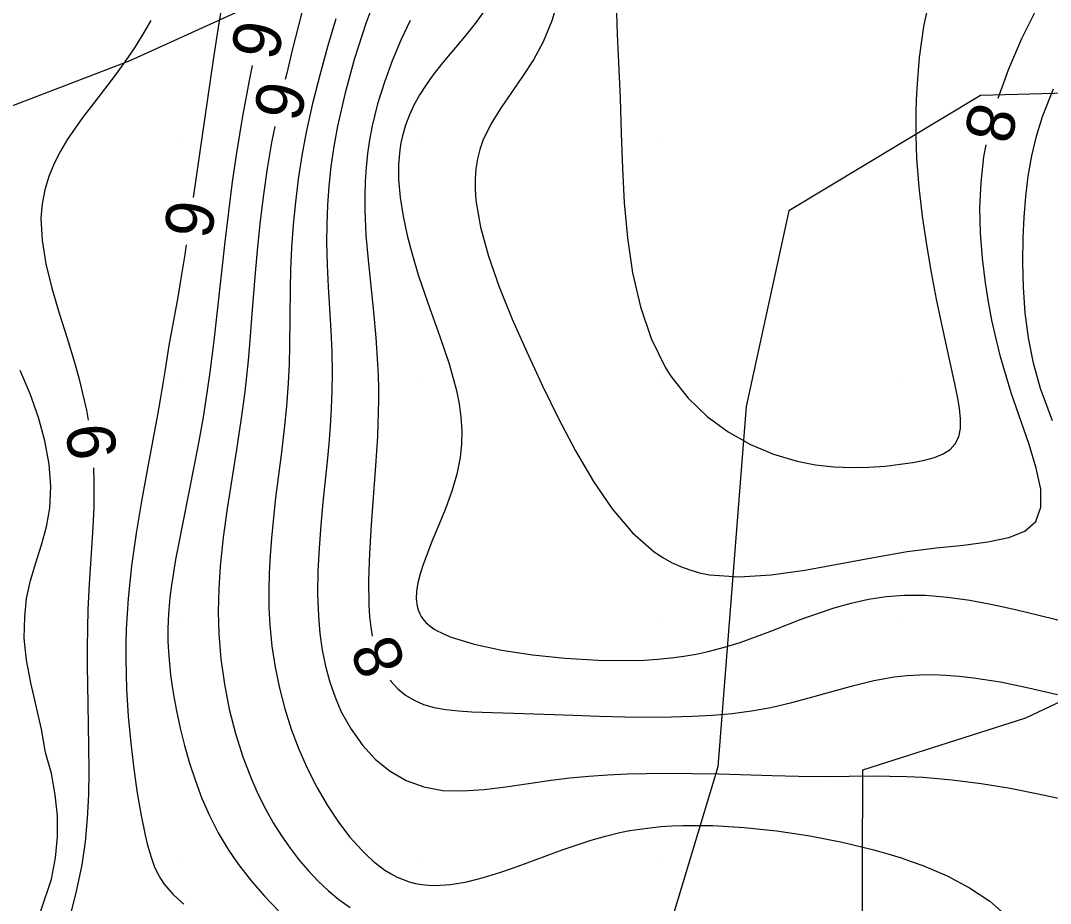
# Model space of a CAD drawing. Extents: x 2602990 to 2605851, y 618069 to 619180.
# Drawn here: x 2603123.31 to 2603166.25, y 618398.06 to 618434.86 of the extents above; entities that cross this region are included whole.
import ezdxf

# ---------------------------------------------------------------- set-up
doc = ezdxf.new("R2010")
doc.units = 0
for name, color, linetype in [('DTM Contours Major', 7, 'Continuous'), ('DTM Contours Major Text', 7, 'Continuous'), ('DTM Contours Minor', 7, 'Continuous'), ('DTM Contours Minor Text', 7, 'Continuous'), ('Exist DTM QL2 LIDAR Elevation Point', 7, 'Continuous'), ('PH Exist DTM Obscure Area', 7, 'Continuous')]:
    doc.layers.add(name, color=color, linetype=linetype)

msp = doc.modelspace()

# ---------------------------------------------------------------- linework, layer by layer
at = {"layer": 'DTM Contours Major'}
for points in [[(2603139.557, 618434.862), (2603139.169, 618434.042), (2603138.806, 618433.184), (2603138.478, 618432.296), (2603138.196, 618431.388), (2603137.969, 618430.469), (2603137.859, 618429.894), (2603137.773, 618429.316), (2603137.711, 618428.733), (2603137.672, 618428.145), (2603137.655, 618427.549), (2603137.659, 618426.945), (2603137.708, 618425.919), (2603137.795, 618424.869), (2603138.02, 618422.722), (2603138.122, 618421.636), (2603138.196, 618420.551), (2603138.216, 618420.05), (2603138.226, 618419.55), (2603138.228, 618419.048), (2603138.221, 618418.542), (2603138.206, 618418.033), (2603138.184, 618417.517), (2603138.11, 618416.302), (2603137.926, 618413.851), (2603137.851, 618412.664), (2603137.813, 618411.535), (2603137.828, 618410.489), (2603137.86, 618410.022), (2603137.91, 618409.58), (2603137.973, 618409.201)], [(2603138.722, 618407.366), (2603138.757, 618407.315), (2603139.038, 618407.006), (2603139.358, 618406.743), (2603139.716, 618406.525), (2603140.113, 618406.354), (2603140.557, 618406.227), (2603141.041, 618406.14), (2603141.562, 618406.085), (2603142.119, 618406.051), (2603144.295, 618405.98), (2603146.356, 618405.901), (2603147.429, 618405.865), (2603148.51, 618405.839), (2603149.584, 618405.828), (2603150.455, 618405.834), (2603151.311, 618405.858), (2603152.152, 618405.906), (2603152.979, 618405.98), (2603153.79, 618406.086), (2603154.587, 618406.227), (2603155.471, 618406.431), (2603156.339, 618406.666), (2603157.196, 618406.911), (2603158.045, 618407.145), (2603158.89, 618407.348), (2603159.736, 618407.499), (2603160.266, 618407.559), (2603160.8, 618407.592), (2603161.341, 618407.598), (2603161.893, 618407.579), (2603162.457, 618407.536), (2603163.036, 618407.469), (2603164.16, 618407.289), (2603165.332, 618407.05), (2603166.536, 618406.768)]]:
    msp.add_lwpolyline(points, dxfattribs=at)
at = {"layer": 'DTM Contours Minor'}
for points in [[(2603135.323, 618436.348), (2603134.637, 618433.625), (2603134.403, 618432.673), (2603134.338, 618432.399)], [(2603138.241, 618436.202), (2603137.708, 618434.734), (2603137.237, 618433.276), (2603136.839, 618431.845), (2603136.522, 618430.458), (2603136.368, 618429.607), (2603136.248, 618428.776), (2603136.161, 618427.963), (2603136.104, 618427.163), (2603136.074, 618426.374), (2603136.07, 618425.592), (2603136.093, 618424.673), (2603136.138, 618423.759), (2603136.245, 618421.946), (2603136.285, 618421.046), (2603136.302, 618420.152), (2603136.292, 618419.421), (2603136.261, 618418.691), (2603136.215, 618417.959), (2603136.155, 618417.223), (2603136.086, 618416.482), (2603135.915, 618414.784), (2603135.826, 618413.828), (2603135.752, 618412.867), (2603135.705, 618411.909), (2603135.692, 618410.96), (2603135.725, 618410.026), (2603135.788, 618409.315), (2603135.887, 618408.619), (2603136.023, 618407.942), (2603136.2, 618407.287), (2603136.418, 618406.656), (2603136.681, 618406.052), (2603137.086, 618405.321), (2603137.563, 618404.654), (2603138.109, 618404.065), (2603138.72, 618403.569), (2603139.39, 618403.18), (2603140.117, 618402.913), (2603140.912, 618402.773), (2603141.754, 618402.748), (2603142.634, 618402.806), (2603143.545, 618402.92), (2603145.427, 618403.198), (2603146.21, 618403.291), (2603146.999, 618403.365), (2603147.794, 618403.419), (2603148.597, 618403.457), (2603149.408, 618403.479), (2603150.228, 618403.486), (2603151.322, 618403.477), (2603152.428, 618403.454), (2603154.648, 618403.39), (2603155.75, 618403.366), (2603156.837, 618403.356), (2603158.877, 618403.372), (2603159.558, 618403.37), (2603160.245, 618403.355), (2603160.943, 618403.322), (2603162.147, 618403.216), (2603163.366, 618403.057), (2603164.572, 618402.857), (2603165.741, 618402.629), (2603166.845, 618402.387)], [(2603131.741, 618435.775), (2603131.53, 618434.488), (2603131.337, 618433.219), (2603130.503, 618427.484)], [(2603145.739, 618435.774), (2603145.452, 618434.845), (2603145.1, 618433.978), (2603144.696, 618433.226), (2603144.242, 618432.523), (2603143.319, 618431.197), (2603142.913, 618430.539), (2603142.588, 618429.862), (2603142.456, 618429.483), (2603142.358, 618429.091), (2603142.293, 618428.684), (2603142.26, 618428.26), (2603142.261, 618427.818), (2603142.295, 618427.354), (2603142.486, 618426.242), (2603142.817, 618425.035), (2603143.265, 618423.754), (2603143.804, 618422.417), (2603144.41, 618421.046), (2603145.06, 618419.66), (2603145.74, 618418.267), (2603146.448, 618416.918), (2603147.192, 618415.65), (2603147.981, 618414.502), (2603148.824, 618413.512), (2603149.729, 618412.718), (2603150.083, 618412.481), (2603150.447, 618412.276), (2603150.824, 618412.101), (2603151.214, 618411.958), (2603151.619, 618411.845), (2603152.039, 618411.761), (2603153.275, 618411.672), (2603154.608, 618411.752), (2603156.005, 618411.948), (2603157.435, 618412.21), (2603158.868, 618412.485), (2603160.272, 618412.724), (2603161.492, 618412.877), (2603162.627, 618412.999), (2603163.644, 618413.129), (2603164.508, 618413.309), (2603165.184, 618413.579), (2603165.638, 618413.982), (2603165.853, 618414.573), (2603165.842, 618415.324), (2603165.658, 618416.206), (2603165.357, 618417.189), (2603164.615, 618419.347), (2603164.383, 618420.089), (2603164.172, 618420.839), (2603163.98, 618421.598), (2603163.81, 618422.365), (2603163.662, 618423.142), (2603163.536, 618423.929), (2603163.41, 618424.955), (2603163.332, 618425.996), (2603163.311, 618427.05), (2603163.355, 618428.113), (2603163.474, 618429.184), (2603163.569, 618429.683)], [(2603148.141, 618435.633), (2603148.18, 618434.298), (2603148.31, 618431.622), (2603148.355, 618430.167), (2603148.4, 618428.69), (2603148.477, 618427.258), (2603148.612, 618425.796), (2603148.828, 618424.343), (2603149.15, 618422.932), (2603149.6, 618421.6), (2603150.201, 618420.383), (2603150.393, 618420.078), (2603150.46, 618419.978), (2603151.148, 618419.114), (2603151.937, 618418.36), (2603152.807, 618417.719), (2603153.737, 618417.191), (2603154.703, 618416.781), (2603155.684, 618416.488), (2603156.459, 618416.34), (2603157.222, 618416.257), (2603157.965, 618416.228), (2603158.678, 618416.244), (2603159.355, 618416.292), (2603159.987, 618416.362), (2603160.514, 618416.439), (2603160.991, 618416.533), (2603161.412, 618416.65), (2603161.771, 618416.799), (2603162.062, 618416.985), (2603162.279, 618417.216), (2603162.424, 618417.512), (2603162.493, 618417.86), (2603162.501, 618418.259), (2603162.457, 618418.704), (2603162.375, 618419.193), (2603162.268, 618419.721), (2603161.72, 618422.199), (2603161.502, 618423.244), (2603161.288, 618424.354), (2603161.088, 618425.513), (2603160.914, 618426.704), (2603160.775, 618427.91), (2603160.683, 618429.114), (2603160.66, 618429.6), (2603160.647, 618430.085), (2603160.643, 618430.57), (2603160.648, 618431.057), (2603160.663, 618431.546), (2603160.686, 618432.04), (2603160.787, 618433.314), (2603160.967, 618434.608), (2603161.246, 618435.906)], [(2603142.692, 618435.332), (2603142.262, 618434.74), (2603141.812, 618434.18), (2603140.917, 618433.114), (2603140.503, 618432.59), (2603140.216, 618432.187), (2603139.956, 618431.778), (2603139.725, 618431.362), (2603139.526, 618430.936), (2603139.361, 618430.5), (2603139.231, 618430.051), (2603139.168, 618429.764), (2603139.12, 618429.472), (2603139.087, 618429.172), (2603139.067, 618428.866), (2603139.062, 618428.553), (2603139.069, 618428.231), (2603139.135, 618427.482), (2603139.258, 618426.7), (2603139.432, 618425.896), (2603139.646, 618425.079), (2603139.891, 618424.26), (2603140.16, 618423.448), (2603140.369, 618422.854), (2603140.788, 618421.691), (2603140.987, 618421.12), (2603141.172, 618420.556), (2603141.337, 618419.995), (2603141.478, 618419.435), (2603141.589, 618418.877), (2603141.664, 618418.321), (2603141.701, 618417.765), (2603141.693, 618417.21), (2603141.636, 618416.653), (2603141.492, 618415.947), (2603141.284, 618415.244), (2603141.034, 618414.55), (2603140.762, 618413.873), (2603140.49, 618413.218), (2603140.24, 618412.594), (2603140.091, 618412.184), (2603139.968, 618411.793), (2603139.876, 618411.422), (2603139.82, 618411.074), (2603139.806, 618410.751), (2603139.838, 618410.453), (2603139.879, 618410.299), (2603139.936, 618410.153), (2603140.011, 618410.015), (2603140.069, 618409.93), (2603140.134, 618409.849), (2603140.208, 618409.77), (2603140.29, 618409.694), (2603140.379, 618409.621), (2603140.478, 618409.551), (2603140.587, 618409.481), (2603140.705, 618409.413), (2603140.832, 618409.348), (2603140.968, 618409.284), (2603141.265, 618409.162), (2603142.224, 618408.866), (2603143.374, 618408.616), (2603144.658, 618408.417), (2603146.017, 618408.276), (2603147.392, 618408.197), (2603148.725, 618408.186), (2603149.312, 618408.205), (2603149.88, 618408.241), (2603150.428, 618408.293), (2603150.96, 618408.362), (2603151.476, 618408.45), (2603151.977, 618408.556), (2603152.654, 618408.734), (2603153.312, 618408.942), (2603153.954, 618409.17), (2603154.588, 618409.411), (2603155.848, 618409.901), (2603156.536, 618410.15), (2603157.234, 618410.379), (2603157.944, 618410.577), (2603158.666, 618410.738), (2603159.404, 618410.852), (2603160.158, 618410.911), (2603161.044, 618410.905), (2603161.952, 618410.829), (2603162.881, 618410.695), (2603163.828, 618410.516), (2603164.791, 618410.304), (2603167.421, 618409.672)], [(2603164.062, 618431.619), (2603164.512, 618432.852), (2603165.058, 618434.107), (2603165.649, 618435.313)], [(2603128.743, 618434.868), (2603128.41, 618434.292), (2603128.055, 618433.728), (2603127.682, 618433.177), (2603127.293, 618432.638), (2603126.947, 618432.181), (2603126.247, 618431.281), (2603125.906, 618430.831), (2603125.579, 618430.377), (2603125.271, 618429.915), (2603124.972, 618429.414), (2603124.71, 618428.897), (2603124.49, 618428.362), (2603124.319, 618427.807), (2603124.206, 618427.227), (2603124.156, 618426.621), (2603124.203, 618425.693), (2603124.367, 618424.715), (2603124.617, 618423.701), (2603124.92, 618422.663), (2603125.247, 618421.614), (2603125.564, 618420.566), (2603125.745, 618419.913), (2603125.908, 618419.263), (2603126.05, 618418.613), (2603126.125, 618418.201)], [(2603136.458, 618434.925), (2603136.111, 618433.766), (2603135.781, 618432.588), (2603135.479, 618431.399), (2603135.217, 618430.212), (2603135.034, 618429.229), (2603134.885, 618428.255), (2603134.766, 618427.291), (2603134.675, 618426.338), (2603134.61, 618425.397), (2603134.569, 618424.469), (2603134.549, 618423.671), (2603134.521, 618421.314), (2603134.501, 618420.532), (2603134.464, 618419.747), (2603134.392, 618418.793), (2603134.295, 618417.835), (2603134.182, 618416.874), (2603133.944, 618414.959), (2603133.836, 618414.009), (2603133.765, 618413.28), (2603133.709, 618412.555), (2603133.672, 618411.832), (2603133.656, 618411.11), (2603133.665, 618410.387), (2603133.703, 618409.661), (2603133.79, 618408.785), (2603133.923, 618407.908), (2603134.102, 618407.035), (2603134.325, 618406.171), (2603134.593, 618405.322), (2603134.904, 618404.492), (2603135.268, 618403.668), (2603135.671, 618402.879), (2603136.106, 618402.136), (2603136.565, 618401.447), (2603137.042, 618400.824), (2603137.53, 618400.274), (2603137.77, 618400.037), (2603138.011, 618399.819), (2603138.255, 618399.622), (2603138.502, 618399.446), (2603138.754, 618399.291), (2603139.01, 618399.157), (2603139.258, 618399.05), (2603139.512, 618398.963), (2603139.773, 618398.895), (2603140.041, 618398.846), (2603140.316, 618398.817), (2603140.601, 618398.807), (2603141.238, 618398.848), (2603141.91, 618398.963), (2603142.608, 618399.138), (2603143.326, 618399.358), (2603144.056, 618399.609), (2603145.936, 618400.304), (2603146.514, 618400.507), (2603147.097, 618400.696), (2603147.69, 618400.866), (2603148.295, 618401.012), (2603148.708, 618401.093), (2603149.129, 618401.161), (2603149.56, 618401.217), (2603150.002, 618401.26), (2603150.457, 618401.29), (2603150.926, 618401.309), (2603152.169, 618401.305), (2603153.483, 618401.23), (2603154.841, 618401.088), (2603156.212, 618400.883), (2603157.57, 618400.617), (2603158.886, 618400.295), (2603159.464, 618400.131), (2603160.03, 618399.953), (2603160.482, 618399.799), (2603160.928, 618399.634), (2603161.937, 618399.206), (2603162.878, 618398.713), (2603163.719, 618398.153), (2603164.43, 618397.522)], [(2603132.968, 618432.987), (2603132.845, 618432.359), (2603132.703, 618431.615), (2603132.566, 618430.868), (2603132.434, 618430.115), (2603132.31, 618429.351), (2603132.133, 618428.134), (2603131.971, 618426.893), (2603131.822, 618425.642), (2603131.363, 618421.515), (2603131.201, 618420.203), (2603131.08, 618419.341), (2603130.918, 618418.328), (2603130.74, 618417.321), (2603130.551, 618416.33), (2603129.875, 618412.949), (2603129.771, 618412.391), (2603129.679, 618411.85), (2603129.599, 618411.325), (2603129.534, 618410.814), (2603129.487, 618410.313), (2603129.46, 618409.876), (2603129.449, 618409.443), (2603129.453, 618409.009), (2603129.474, 618408.54), (2603129.512, 618408.066), (2603129.565, 618407.585), (2603129.633, 618407.096), (2603129.716, 618406.598), (2603129.812, 618406.089), (2603129.965, 618405.371), (2603130.146, 618404.639), (2603130.355, 618403.9), (2603130.596, 618403.163), (2603130.872, 618402.435), (2603131.184, 618401.724), (2603131.363, 618401.361), (2603131.553, 618401.004), (2603131.755, 618400.652), (2603131.97, 618400.306), (2603132.196, 618399.964), (2603132.436, 618399.625), (2603132.935, 618398.984), (2603133.479, 618398.359), (2603134.064, 618397.756)], [(2603166.337, 618418.17), (2603165.835, 618419.52), (2603165.546, 618420.574), (2603165.336, 618421.628), (2603165.197, 618422.68), (2603165.119, 618423.728), (2603165.092, 618424.769), (2603165.107, 618425.801), (2603165.149, 618426.67), (2603165.219, 618427.53), (2603165.325, 618428.38), (2603165.472, 618429.219), (2603165.666, 618430.045), (2603165.913, 618430.857), (2603166.373, 618432.009)], [(2603133.908, 618430.446), (2603133.777, 618429.782), (2603133.593, 618428.698), (2603133.435, 618427.607), (2603133.3, 618426.515), (2603133.184, 618425.427), (2603133.085, 618424.349), (2603132.949, 618422.634), (2603132.849, 618421.34), (2603132.794, 618420.693), (2603132.73, 618420.04), (2603132.656, 618419.378), (2603132.496, 618418.189), (2603132.31, 618416.976), (2603132.115, 618415.75), (2603131.926, 618414.525), (2603131.761, 618413.311), (2603131.635, 618412.121), (2603131.598, 618411.642), (2603131.571, 618411.168), (2603131.555, 618410.697), (2603131.55, 618410.228), (2603131.556, 618409.759), (2603131.575, 618409.29), (2603131.661, 618408.243), (2603131.807, 618407.196), (2603132.01, 618406.161), (2603132.268, 618405.148), (2603132.576, 618404.169), (2603132.934, 618403.234), (2603133.215, 618402.603), (2603133.517, 618402), (2603133.841, 618401.425), (2603134.184, 618400.878), (2603134.547, 618400.358), (2603134.927, 618399.865), (2603135.314, 618399.411), (2603135.719, 618398.985), (2603136.141, 618398.588), (2603136.583, 618398.223), (2603137.044, 618397.891)], [(2603130.212, 618425.506), (2603130.153, 618425.114), (2603130.006, 618424.189), (2603129.861, 618423.334), (2603129.491, 618421.309), (2603129.317, 618420.228), (2603129.13, 618419.064), (2603129.019, 618418.426), (2603128.587, 618416.123), (2603128.352, 618414.832), (2603128.129, 618413.49), (2603127.937, 618412.127), (2603127.795, 618410.775), (2603127.749, 618410.129), (2603127.717, 618409.492), (2603127.701, 618408.861), (2603127.698, 618408.236), (2603127.707, 618407.614), (2603127.729, 618406.994), (2603127.798, 618405.859), (2603127.9, 618404.745), (2603128.028, 618403.673), (2603128.176, 618402.662), (2603128.338, 618401.731), (2603128.508, 618400.902), (2603128.593, 618400.542), (2603128.681, 618400.208), (2603128.777, 618399.898), (2603128.883, 618399.61), (2603129.004, 618399.343), (2603129.143, 618399.094), (2603129.296, 618398.868), (2603129.469, 618398.654), (2603129.663, 618398.445), (2603129.876, 618398.238), (2603130.11, 618398.028)], [(2603123.48, 618410), (2603123.554, 618410.774), (2603123.721, 618411.524), (2603123.942, 618412.262), (2603124.176, 618413), (2603124.385, 618413.752), (2603124.529, 618414.529), (2603124.574, 618415.433), (2603124.502, 618416.374), (2603124.325, 618417.34), (2603124.056, 618418.32), (2603123.709, 618419.303), (2603123.296, 618420.278)], [(2603126.344, 618416.215), (2603126.369, 618415.612), (2603126.358, 618414.565), (2603126.309, 618413.506), (2603126.171, 618411.374), (2603126.116, 618410.312), (2603126.093, 618409.525), (2603126.084, 618408.741), (2603126.087, 618407.958), (2603126.113, 618406.384), (2603126.146, 618404.591), (2603126.151, 618403.588), (2603126.134, 618402.587), (2603126.086, 618401.595), (2603125.999, 618400.622), (2603125.863, 618399.674), (2603125.645, 618398.63), (2603125.18, 618396.779)], [(2603124.14, 618397.704), (2603124.591, 618399.065), (2603124.768, 618399.957), (2603124.851, 618400.839), (2603124.845, 618401.716), (2603124.756, 618402.592), (2603124.591, 618403.47), (2603124.354, 618404.354), (2603124.177, 618405.319), (2603123.737, 618407.25), (2603123.556, 618408.196), (2603123.457, 618409.116), (2603123.48, 618410)]]:
    msp.add_lwpolyline(points, dxfattribs=at)
at = {"layer": 'Exist DTM QL2 LIDAR Elevation Point'}
for p, q in [((2603130, 618430), (2603130, 618430)), ((2603140, 618430), (2603140, 618430)), ((2603150, 618430), (2603150, 618430)), ((2603160, 618430), (2603160, 618430)), ((2603130, 618420), (2603130, 618420)), ((2603140, 618420), (2603140, 618420)), ((2603150, 618420), (2603150, 618420)), ((2603160, 618420), (2603160, 618420)), ((2603130, 618410), (2603130, 618410)), ((2603140, 618410), (2603140, 618410)), ((2603150, 618410), (2603150, 618410)), ((2603160, 618410), (2603160, 618410)), ((2603130, 618400), (2603130, 618400)), ((2603140, 618400), (2603140, 618400)), ((2603150, 618400), (2603150, 618400)), ((2603160, 618400), (2603160, 618400))]:
    msp.add_line(p, q, dxfattribs=at)
at = {"layer": 'PH Exist DTM Obscure Area'}
for points in [[(2603122.912, 618431.294), (2603127.871, 618433.194), (2603132.28, 618435.19), (2603134.13, 618438.847), (2603133.978, 618445.263), (2603133.268, 618450.033), (2603128.241, 618453.082), (2603122.552, 618451.734)], [(2603158.394, 618395.561), (2603158.433, 618403.627), (2603165.226, 618405.794), (2603173.861, 618409.877), (2603177.085, 618413.253), (2603178.307, 618419.571), (2603176.417, 618426.82), (2603172.042, 618431.974), (2603163.334, 618431.741), (2603155.337, 618426.922), (2603153.556, 618418.773), (2603152.384, 618403.748), (2603150.149, 618396.334)]]:
    msp.add_lwpolyline(points, dxfattribs=at)

# ---------------------------------------------------------------- texts
at = {"layer": 'DTM Contours Major Text'}
msp.add_text('8', height=2, rotation=112.2141, dxfattribs=at).set_placement((2603139.416, 618408.013))
at = {"layer": 'DTM Contours Minor Text'}
for s, rotation, p in [('9', 78.8025, (2603134.015, 618433.133)), ('9', 77.5602, (2603134.95, 618430.571)), ('8', 255.7025, (2603162.981, 618431.538)), ('9', 81.628, (2603131.253, 618425.702)), ('9', 96.2854, (2603127.336, 618416.672))]:
    msp.add_text(s, height=2, rotation=rotation, dxfattribs=at).set_placement(p)

doc.saveas('drawing.dxf')
